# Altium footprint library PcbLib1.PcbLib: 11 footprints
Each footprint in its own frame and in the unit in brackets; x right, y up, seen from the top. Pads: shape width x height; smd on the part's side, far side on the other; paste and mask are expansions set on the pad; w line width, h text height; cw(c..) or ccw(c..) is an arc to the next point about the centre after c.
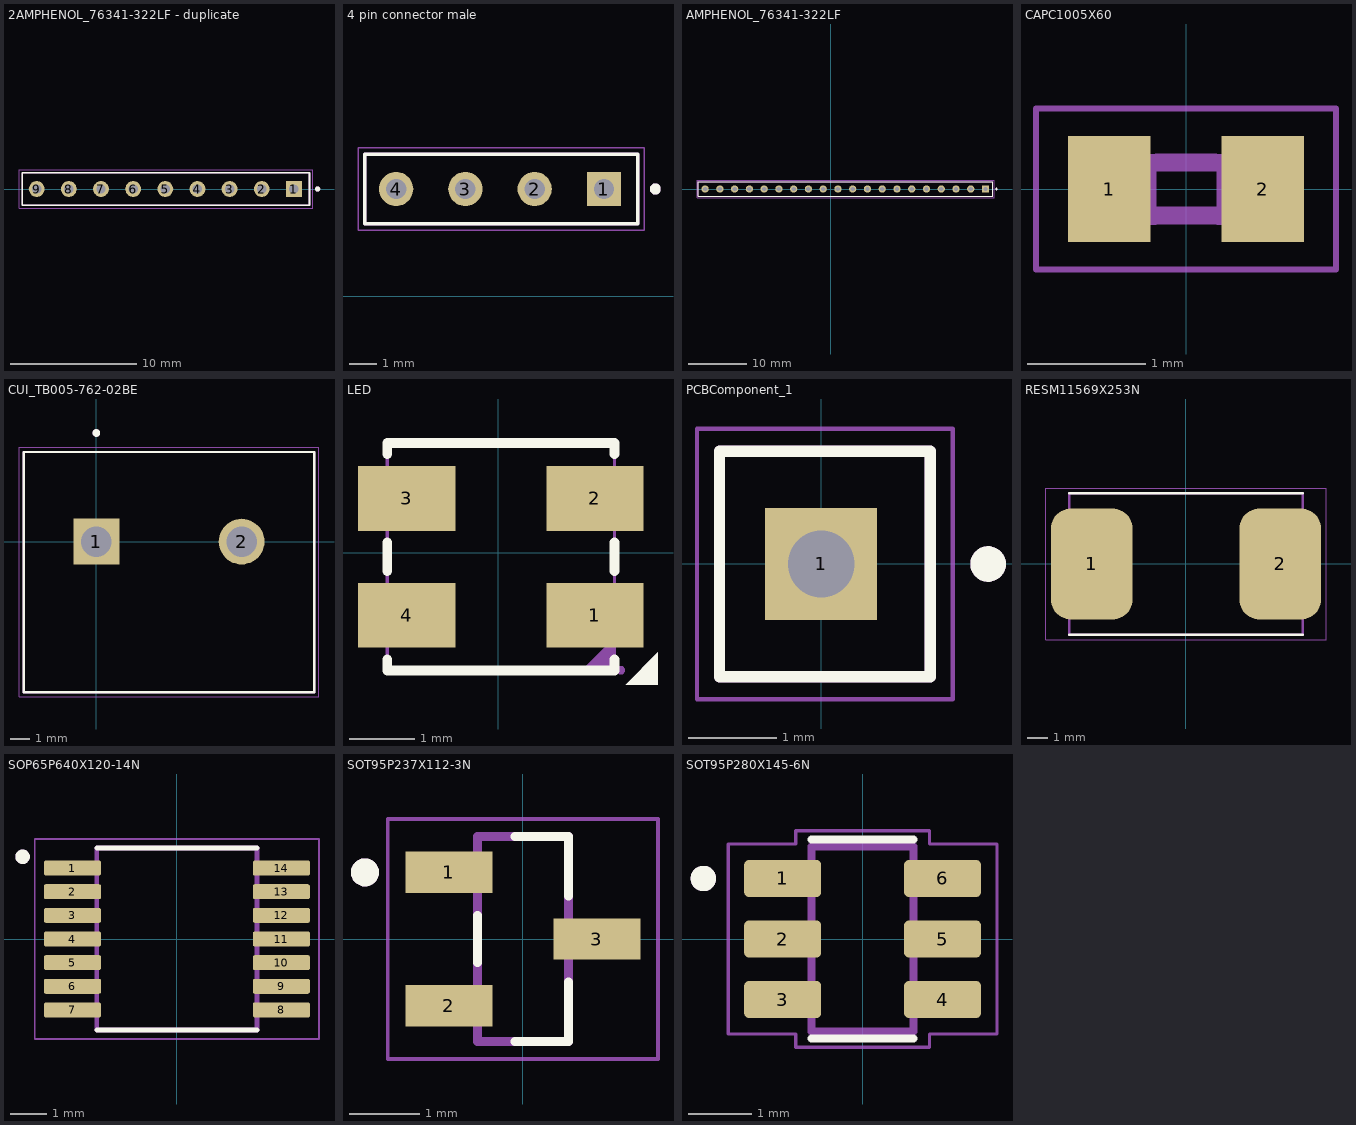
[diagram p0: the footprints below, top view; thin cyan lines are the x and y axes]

## 2AMPHENOL_76341-322LF - duplicate [mm]
pads (9):
  rect 1.258x1.258 / inner round 1.258 / far side rect 1.258x1.258 hole 0.75: 1(26.67,0)
  round 1.258 hole 0.75: 2(24.13,0) 3(21.59,0) 4(19.05,0) 5(16.51,0) 6(13.97,0) 7(11.43,0) 8(8.89,0) 9(6.35,0)
Top Overlay:
  circle w0.2: c28.55,0 r0.1
  lines w0.127: 5.207,-1.27 5.207,1.27 27.9,1.27 27.9,-1.27 5.207,-1.27
Mechanical 13:
  circle w0.2: c28.55,0 r0.1
  lines w0.127: 5.207,-1.27 5.207,1.27 27.9,1.27 27.9,-1.27 ; 5.207,-1.27 27.9,-1.27 ; 5.207,-1.27 27.9,-1.27
Mechanical 15:
  lines w0.05: 4.953,-1.52 28.15,-1.52 28.15,1.52 4.953,1.52 4.953,-1.52

## 4 pin connector male [mm]
pads (4):
  rect 1.258x1.258 / inner round 1.258 / far side rect 1.258x1.258 hole 0.75: 1(22.86,3.937)
  round 1.258 hole 0.75: 2(20.32,3.937) 3(17.78,3.937) 4(15.24,3.937)
Top Overlay:
  circle w0.2: c24.74,3.937 r0.1
  lines w0.127: 14.097,2.667 24.09,2.667 24.09,5.207 14.097,5.207 14.097,2.667
Mechanical 13:
  circle w0.2: c24.74,3.937 r0.1
  lines w0.127: 14.224,2.667 24.09,2.667 ; 24.09,2.667 24.09,5.207 14.097,5.207 14.097,2.667 24.09,2.667
Mechanical 15:
  lines w0.05: 13.843,2.417 24.34,2.417 24.34,5.457 13.843,5.457 13.843,2.417

## AMPHENOL_76341-322LF [mm]
pads (20):
  rect 1.258x1.258 / inner round 1.258 / far side rect 1.258x1.258 hole 0.75: 01(26.67,0)
  round 1.258 hole 0.75: 02(24.13,0) 03(21.59,0) 04(19.05,0) 05(16.51,0) 06(13.97,0) 07(11.43,0) 08(8.89,0) 09(6.35,0) 10(3.81,0) 11(1.27,0) 12(-1.27,0) 13(-3.81,0) 14(-6.35,0) 15(-8.89,0) 16(-11.43,0) 17(-13.97,0) 18(-16.51,0) 19(-19.05,0) 20(-21.59,0)
Top Overlay:
  circle w0.2: c28.55,0 r0.1
  lines w0.127: -22.733,-1.27 27.9,-1.27 27.9,1.27 -22.733,1.27 -22.733,-1.27
Mechanical 13:
  circle w0.2: c28.55,0 r0.1
  lines w0.127: -22.733,-1.27 27.9,-1.27 ; -22.733,-1.27 27.9,-1.27 ; -22.733,-1.27 -22.733,1.27 27.9,1.27 27.9,-1.27
Mechanical 15:
  lines w0.05: -22.987,-1.52 -22.987,1.52 28.15,1.52 28.15,-1.52 -22.987,-1.52

## CAPC1005X60 [mm]
pads (2):
  rect 0.7x0.9 smd: 1(-0.65,0) 2(0.65,0)
Mechanical 13:
  region: -0.254,-0.305 -0.555,-0.305 -0.555,0.295 -0.254,0.295
  region: 0.559,-0.305 0.259,-0.305 0.259,0.295 0.559,0.295
  lines w0.152: -0.245,-0.224 0.245,-0.224 ; -0.245,0.224 0.245,0.224
Mechanical 15:
  lines w0.051: -1.273,-0.683 1.273,-0.683 1.273,0.683 -1.273,0.683 -1.273,-0.683
3D body "step_temp.STEP": height 0.4, standoff 0, extent -0.5,-0.25 0.5,0.25

## CUI_TB005-762-02BE [mm]
pads (2):
  rect 2.4x2.4 / inner round 2.4 / far side rect 2.4x2.4 hole 1.6: 1(0,0)
  round 2.4 hole 1.6: 2(7.62,0)
Top Overlay:
  circle w0.2: c0,5.7 r0.1
  lines w0.127: -3.81,-7.9 11.43,-7.9 11.43,4.7 -3.81,4.7 -3.81,-7.9
Mechanical 13:
  circle w0.2: c0,5.7 r0.1
  lines w0.127: -3.81,-7.9 11.43,-7.9 11.43,4.7 -3.81,4.7 -3.81,-7.9
Mechanical 15:
  lines w0.05: -4.06,-8.15 -4.06,4.95 11.68,4.95 11.68,-8.15 -4.06,-8.15
3D body "step_temp.STEP": height 21.7, standoff -4.75, extent -4.318,-7.697 11.522,4.903

## LED [mm]
pads (4):
  rect 1.5x1 smd: 1(1.491,-0.96) 2(1.491,0.841) 3(-1.409,0.841) 4(-1.409,-0.96)
Top Overlay:
  region: 1.963,-2.032 2.463,-2.032 2.463,-1.532
  lines w0.152: -1.709,-1.64 -1.709,-1.809 1.791,-1.809 1.791,-1.64 ; -1.709,-0.279 -1.709,0.16 ; -1.709,1.521 -1.709,1.691 1.791,1.691 1.791,1.521 ; 1.791,-0.279 1.791,0.16
Mechanical 6:
  drawing of 21 lines, arcs and shapes, not listed
Mechanical 15:
  region: 1.951,-1.809 1.951,-1.834 1.916,-1.869 1.866,-1.869 1.831,-1.834 1.831,-1.809 1.831,-1.785 1.866,-1.749 1.916,-1.749 1.951,-1.785 1.951,-1.809
  region: -0.909,0.441 -1.809,0.441 -1.809,1.241 -0.909,1.241
  region: -0.909,-1.36 -1.809,-1.36 -1.809,-0.56 -0.909,-0.56
  region: 1.891,0.441 0.991,0.441 0.991,1.241 1.891,1.241
  region: 1.891,-1.36 0.991,-1.36 0.991,-0.56 1.891,-0.56
  lines w0.051: -1.709,-1.809 -1.709,1.691 1.791,1.691 1.791,-1.809 -1.709,-1.809
3D body "SMD3535 RGB.stp": height 1, standoff 0, extent -1.723,-1.801 1.977,1.699

## PCBComponent_1 [mm]
pads (1):
  rect 1.258x1.258 / inner round 1.258 / far side rect 1.258x1.258 hole 0.75: 1(0,0)
Top Overlay:
  circle w0.2: c1.88,0 r0.1
  lines w0.127: -1.143,-1.27 1.23,-1.27 1.23,1.27 -1.143,1.27 -1.143,-1.27
Mechanical 13:
  circle w0.2: c1.88,0 r0.1
  lines w0.127: -1.143,-1.27 1.23,-1.27 ; -1.143,-1.27 1.23,-1.27 ; -1.143,-1.27 -1.143,1.27 1.23,1.27 1.23,-1.27
Mechanical 15:
  lines w0.05: -1.397,-1.52 -1.397,1.52 1.48,1.52 1.48,-1.52 -1.397,-1.52

## RESM11569X253N [mm]
pads (2):
  rrect50% 4.04x5.51 smd: 1(-4.665,0) 2(4.665,0)
Top Overlay:
  lines w0.127: -5.78,-3.49 5.78,-3.49 ; -5.78,3.49 5.78,3.49
Mechanical 13:
  lines w0.127: -5.78,-3.49 -5.78,3.49 5.78,3.49 5.78,-3.49 -5.78,-3.49
Mechanical 15:
  lines w0.05: -6.935,-3.74 -6.935,3.74 6.935,3.74 6.935,-3.74 -6.935,-3.74
3D body "WSR 2.STEP": height 2.42, standoff 0.01, extent -5.78,-3.556 5.78,3.424

## SOP65P640X120-14N [mm]
pads (14):
  rrect25% 1.57x0.41 smd: 1(-2.87,1.95) 2(-2.87,1.3) 3(-2.87,0.65) 4(-2.87,0) 5(-2.87,-0.65) 6(-2.87,-1.3) 7(-2.87,-1.95) 8(2.87,-1.95) 9(2.87,-1.3) 10(2.87,-0.65) 11(2.87,0) 12(2.87,0.65) 13(2.87,1.3) 14(2.87,1.95)
Top Overlay:
  circle w0.2: c-4.24,2.26 r0.1
  lines w0.127: -2.2,-2.5 2.2,-2.5 ; -2.2,2.5 2.2,2.5
Mechanical 13:
  circle w0.2: c-4.24,2.26 r0.1
  lines w0.127: -2.2,-2.5 -2.2,2.5 2.2,2.5 2.2,-2.5 -2.2,-2.5
Mechanical 15:
  lines w0.05: -3.905,-2.75 -3.905,2.75 3.905,2.75 3.905,-2.75 -3.905,-2.75
3D body "step_temp.STEP": height 1.2, standoff 0, extent -3.2,-2.5 3.2,2.5

## SOT95P237X112-3N [mm]
height 1.12
pads (3):
  rect 1.24x0.59 smd: 1(-1.055,0.95) 2(-1.055,-0.95) 3(1.055,0)
Top Overlay:
  circle w0.2: c-2.25,0.95 r0.1
  lines w0.127: -0.65,-0.335 -0.65,0.335 ; -0.115,-1.46 0.65,-1.46 0.65,-0.615 ; -0.115,1.46 0.65,1.46 0.65,0.615
Mechanical 13:
  circle w0.2: c-2.25,0.95 r0.1
  lines w0.127: -0.65,-1.46 0.65,-1.46 0.65,1.46 -0.65,1.46 -0.65,-1.46
Mechanical 15:
  lines w0.05: -1.925,-1.71 1.925,-1.71 1.925,1.71 -1.925,1.71 -1.925,-1.71
3D body "step_temp.STEP": height 1.12, standoff 0, extent -1.185,-1.46 1.185,1.46

## SOT95P280X145-6N [mm]
pads (6):
  rrect25% 1.21x0.58 smd: 1(-1.255,0.95) 2(-1.255,0) 3(-1.255,-0.95) 4(1.255,-0.95) 5(1.255,0) 6(1.255,0.95)
Top Overlay:
  circle w0.2: c-2.5,0.95 r0.1
  lines w0.127: -0.8,-1.56 0.8,-1.56 ; -0.8,1.56 0.8,1.56
Mechanical 13:
  circle w0.2: c-2.5,0.95 r0.1
  lines w0.127: -0.8,-1.45 -0.8,1.45 0.8,1.45 0.8,-1.45 -0.8,-1.45
Mechanical 15:
  lines w0.05: -2.11,-1.49 -2.11,1.49 -1.05,1.49 -1.05,1.7 1.05,1.7 1.05,1.49 2.11,1.49 2.11,-1.49 1.05,-1.49 1.05,-1.7 -1.05,-1.7 -1.05,-1.49 -2.11,-1.49
3D body "step_temp.STEP": height 1.45, standoff 0, extent -1.4,-1.45 1.4,1.45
